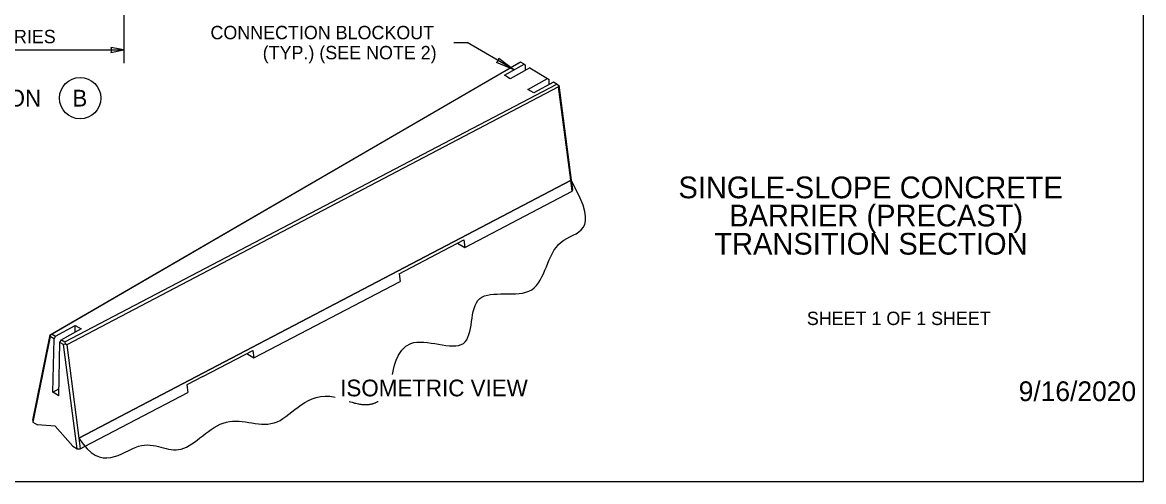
# Model space of a CAD drawing. Extents: x 99862 to 103151, y 100000 to 102076.
# Drawn here: x 101810 to 103151, y 100000 to 100549 of the extents above; entities that cross this region are included whole.
import ezdxf

# ---------------------------------------------------------------- set-up
doc = ezdxf.new("R2010")
doc.units = 0
for name, color, linetype in [('Level 1', 7, 'Continuous'), ('Level 15', 7, 'Continuous'), ('Level 2', 7, 'Continuous'), ('Level 20', 7, 'Continuous'), ('Level 6', 7, 'Continuous'), ('Level 62', 7, 'Continuous'), ('Level 9', 7, 'Continuous')]:
    doc.layers.add(name, color=color, linetype=linetype)

msp = doc.modelspace()

# ---------------------------------------------------------------- linework, layer by layer
at = {"layer": 'Level 1'}
msp.add_lwpolyline([(99862, 99999.5), (103151, 99999.5), (103151, 102075.5), (99862, 102075.5)], close=True, dxfattribs=at)
at = {"layer": 'Level 15'}
for p, q in [((101931.3, 100640), (101931.3, 100500)), ((102325.8, 100524.8), (102341.8, 100524.8)), ((102398.1, 100492.3), (102341.8, 100524.8)), ((101692, 100516), (101931.3, 100516))]:
    msp.add_line(p, q, dxfattribs=at)
for points in [[(101931.3, 100516), (101915.6, 100519.1), (101916.3, 100516), (101915.6, 100512.9)], [(102398.1, 100492.3), (102376.9, 100501.1), (102379.3, 100503.2), (102379.9, 100506.3)]]:
    msp.add_lwpolyline(points, close=True, dxfattribs=at)
at = {"layer": 'Level 2'}
for p, q in [((101843.2, 100175.1), (102403.7, 100500.5)), ((102405.8, 100501.2), (101845.4, 100175.9)), ((102386.4, 100485.8), (102409.9, 100498.8)), ((102416.9, 100494.5), (102393.5, 100481.6)), ((102405.6, 100501.4), (102403.7, 100500.5)), ((102405.6, 100501.4), (102405.8, 100501.2)), ((102409.9, 100498.8), (102405.8, 100501.2)), ((102409.9, 100498.8), (102411.6, 100497.7)), ((102411.5, 100491.5), (102411.6, 100497.7)), ((102416.9, 100494.5), (102439.9, 100480.7)), ((102393.5, 100481.6), (102386.4, 100485.8)), ((102414.6, 100468.8), (102438.1, 100481.7)), ((102439.8, 100474.5), (102439.9, 100480.7)), ((101860.7, 100166.6), (102449.3, 100475)), ((102451.3, 100471.7), (101862.8, 100163.3)), ((102421.7, 100464.5), (102414.6, 100468.8)), ((102445.2, 100477.5), (102421.7, 100464.5)), ((102449.3, 100475), (102445.2, 100477.5)), ((102449.3, 100475), (102451.2, 100473.8)), ((102451.2, 100473.8), (102451.4, 100473.7)), ((102451.2, 100473.8), (102451.3, 100471.7)), ((102465.9, 100360), (102451.3, 100471.7)), ((102451.4, 100473.7), (102466.2, 100360.2)), ((102467.6, 100347), (102465.9, 100360)), ((102466.2, 100360.2), (102467.7, 100349.1)), ((102338.9, 100279.6), (102467.6, 100347)), ((102467.7, 100349.1), (102467.6, 100347)), ((102305.2, 100271.6), (102330.3, 100284.8)), ((102330.3, 100284.8), (102337.7, 100288.6)), ((102330.3, 100284.8), (102338.9, 100279.6)), ((102337.7, 100288.6), (102338.9, 100279.6)), ((102260.4, 100248.1), (102305.2, 100271.6)), ((102086.8, 100147.5), (102261.6, 100239.1)), ((102260.4, 100248.2), (102261.6, 100239.1)), ((101849.5, 100173.4), (101873, 100186.3)), ((101872.8, 100178.1), (101873, 100186.3)), ((101873, 100186.3), (101880.1, 100182.1)), ((101822.5, 100072.8), (101843.2, 100175.1)), ((101843.2, 100173), (101822.5, 100070.7)), ((101843.2, 100175.1), (101843.4, 100175)), ((101843.4, 100175), (101843.2, 100173)), ((101847.7, 100170.3), (101843.2, 100173)), ((101843.4, 100175), (101845.4, 100175.9)), ((101845.4, 100175.9), (101849.5, 100173.4)), ((101846.4, 100106.4), (101847.7, 100170.3)), ((101849.5, 100173.4), (101847.7, 100170.3)), ((101880.1, 100182.1), (101856.6, 100169.1)), ((101853.5, 100102.1), (101854.7, 100166.1)), ((101854.7, 100166.1), (101856.6, 100169.1)), ((101859.2, 100163.4), (101854.7, 100166.1)), ((101856.6, 100169.1), (101860.7, 100166.6)), ((101859.2, 100163.4), (101860.9, 100164.5)), ((101875.4, 100038.8), (101859.2, 100163.4)), ((101860.7, 100166.6), (101860.9, 100164.5)), ((101862.8, 100163.3), (101860.9, 100164.5)), ((101862.8, 100163.3), (101877.4, 100051.4)), ((102025.7, 100125.1), (102085.6, 100156.5)), ((102085.6, 100156.5), (102086.8, 100147.5)), ((102078.2, 100152.7), (102086.8, 100147.5)), ((102025.7, 100125.3), (102006.6, 100115.2)), ((101846.4, 100106.4), (101853.6, 100110.4)), ((101853.5, 100102.1), (101846.4, 100106.4)), ((101884.2, 100041.4), (102007.8, 100106.1)), ((102006.6, 100115.2), (102007.8, 100106.1)), ((101822.5, 100072.8), (101822.5, 100070.7)), ((101822.5, 100070.7), (101827.8, 100067.5)), ((101849.2, 100065.7), (101827.8, 100067.5)), ((101870.2, 100042), (101849.2, 100065.7)), ((101877.4, 100051.4), (101879.1, 100038.7)), ((101870.2, 100042), (101875.4, 100038.8)), ((101875.4, 100038.8), (101879.1, 100038.7)), ((101879.1, 100038.7), (101884.2, 100041.4))]:
    msp.add_line(p, q, dxfattribs=at)
at = {"layer": 'Level 6'}
msp.add_line((101877.4, 100051.4), (102466.2, 100360.2), dxfattribs=at)
msp.add_lwpolyline([(102466.2, 100360.2), (101877.5, 100051.4)], dxfattribs=at)
for points, degree in [([(102252.7, 100127.5), (102253.1, 100129.9), (102260.1, 100186.7), (102356.6, 100140.3), (102337.6, 100240.9), (102434.6, 100207.2), (102438.6, 100305), (102503.8, 100294.6), (102466.2, 100360.2)], 3), ([(101877.5, 100051.4), (101903.8, 100009), (101953.8, 100062), (101998.3, 100019.9), (102051.8, 100088.5), (102117.3, 100050.1), (102149.6, 100107.9), (102184, 100100.6)], 3), ([(102200.9, 100095.5), (102222.5, 100087.8), (102235.4, 100095.5)], 2)]:
    msp.add_open_spline(points, degree=degree, dxfattribs=at)
at = {"layer": 'Level 9'}
msp.add_circle((101878.9, 100458.3), 24.7, dxfattribs=at)

# ---------------------------------------------------------------- texts
at = {"layer": 'Level 15'}
msp.add_text('9/16/2020', height=23.62, dxfattribs=at).set_placement((103001.6, 100095.8))
at = {"layer": 'Level 20'}
for s, height, p in [('CONNECTION BLOCKOUT', 16, (102034.8, 100528.8)), ('VARIES', 16, (101771.2, 100524)), ('(TYP.) (SEE NOTE 2)', 16, (102097.3, 100504.8)), ('SECTION', 20, (101713.4, 100448.3)), ('B', 20, (101869.6, 100448.3)), ('ISOMETRIC VIEW', 20, (102190, 100101.5))]:
    msp.add_text(s, height=height, dxfattribs=at).set_placement(p)
at = {"layer": 'Level 62'}
for s, height, p in [('SINGLE-SLOPE CONCRETE', 26, (102594.6, 100338.5)), ('BARRIER (PRECAST)', 26, (102655.3, 100304.8)), ('TRANSITION SECTION', 26, (102637.5, 100271.1)), ('SHEET 1 OF 1 SHEET', 16, (102748.2, 100186.8))]:
    msp.add_text(s, height=height, dxfattribs=at).set_placement(p)

doc.saveas('drawing.dxf')
